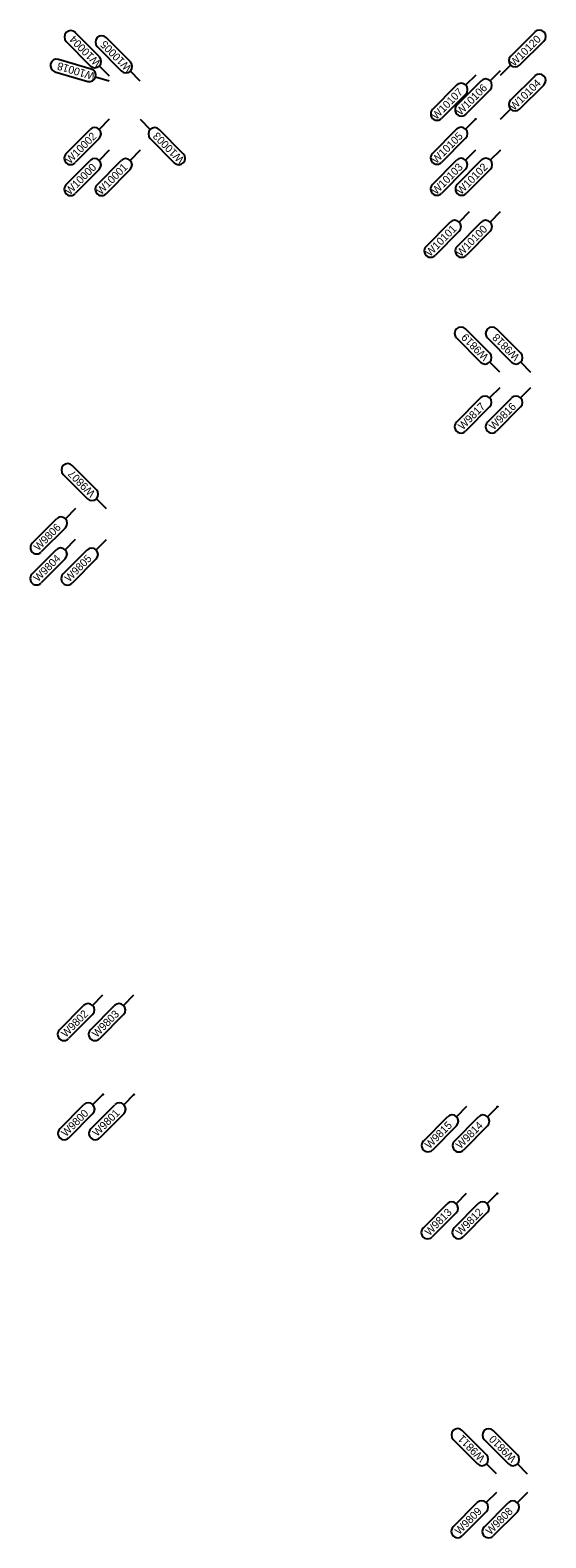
# Model space of a CAD drawing. Extents: x 12479652 to 12487250, y 9842710 to 9846560.
# Drawn here: x 12483665.7 to 12483748.9, y 9844668.9 to 9844912 of the extents above; entities that cross this region are included whole.
import ezdxf

# ---------------------------------------------------------------- set-up
doc = ezdxf.new("R2010")
doc.units = 0
doc.layers.add('Default', color=7, linetype='Continuous')
doc.layers.add('TextAlignmentLrg', color=7, linetype='Continuous')

msp = doc.modelspace()

# ---------------------------------------------------------------- linework, layer by layer
at = {"layer": 'Default'}
for p, q in [((12483676.91, 9844907.74), (12483673.03, 9844911.66)), ((12483681.91, 9844906.91), (12483678.03, 9844910.84)), ((12483747.18, 9844911.75), (12483743.26, 9844907.87)), ((12483671.57, 9844910.22), (12483675.45, 9844906.29)), ((12483676.57, 9844909.39), (12483680.45, 9844905.47)), ((12483744.7, 9844906.41), (12483748.62, 9844910.29)), ((12483675.61, 9844905.75), (12483670.32, 9844907.31)), ((12483678.52, 9844904.65), (12483676.9, 9844906.28)), ((12483741.61, 9844904.8), (12483743.25, 9844906.42)), ((12483669.74, 9844905.34), (12483675.03, 9844903.79)), ((12483678.51, 9844903.83), (12483676.31, 9844904.48)), ((12483683.51, 9844903.82), (12483681.9, 9844905.46)), ((12483734.59, 9844899.95), (12483738.48, 9844903.87)), ((12483737.61, 9844904.81), (12483735.99, 9844903.18)), ((12483741.55, 9844905.5), (12483739.93, 9844903.87)), ((12483747.17, 9844904.65), (12483743.25, 9844900.78)), ((12483730.65, 9844899.26), (12483734.54, 9844903.18)), ((12483736, 9844901.73), (12483732.11, 9844897.82)), ((12483739.93, 9844902.42), (12483736.04, 9844898.51)), ((12483744.69, 9844899.32), (12483748.61, 9844903.19)), ((12483741.6, 9844897.71), (12483743.24, 9844899.32)), ((12483678.51, 9844897.68), (12483676.88, 9844896.05)), ((12483683.51, 9844897.67), (12483685.12, 9844896.03)), ((12483737.6, 9844897.71), (12483735.98, 9844896.08)), ((12483671.54, 9844892.13), (12483675.43, 9844896.04)), ((12483676.89, 9844894.59), (12483673, 9844890.68)), ((12483685.11, 9844894.58), (12483688.99, 9844890.66)), ((12483690.45, 9844892.1), (12483686.57, 9844896.02)), ((12483730.64, 9844892.17), (12483734.53, 9844896.08)), ((12483735.99, 9844894.63), (12483732.1, 9844890.72)), ((12483678.5, 9844892.68), (12483676.88, 9844891.05)), ((12483683.5, 9844892.67), (12483681.88, 9844891.04)), ((12483737.59, 9844892.71), (12483735.97, 9844891.08)), ((12483741.59, 9844892.71), (12483739.97, 9844891.08)), ((12483671.54, 9844887.13), (12483675.42, 9844891.04)), ((12483676.88, 9844889.59), (12483672.99, 9844885.68)), ((12483676.54, 9844887.12), (12483680.42, 9844891.03)), ((12483681.88, 9844889.59), (12483677.99, 9844885.67)), ((12483730.63, 9844887.17), (12483734.52, 9844891.08)), ((12483735.98, 9844889.63), (12483732.09, 9844885.72)), ((12483734.63, 9844887.16), (12483738.52, 9844891.07)), ((12483739.98, 9844889.63), (12483736.09, 9844885.71)), ((12483736.56, 9844882.72), (12483734.94, 9844881.08)), ((12483741.56, 9844882.72), (12483739.94, 9844881.08)), ((12483729.6, 9844877.17), (12483733.49, 9844881.08)), ((12483734.95, 9844879.63), (12483731.06, 9844875.72)), ((12483734.6, 9844877.17), (12483738.49, 9844881.08)), ((12483739.95, 9844879.63), (12483736.06, 9844875.72)), ((12483734.53, 9844862.42), (12483738.41, 9844858.51)), ((12483739.87, 9844859.95), (12483735.98, 9844863.87)), ((12483739.53, 9844862.41), (12483743.41, 9844858.49)), ((12483744.87, 9844859.94), (12483740.98, 9844863.85)), ((12483741.49, 9844856.87), (12483739.87, 9844858.5)), ((12483746.49, 9844856.86), (12483744.87, 9844858.49)), ((12483734.52, 9844848.82), (12483738.41, 9844852.74)), ((12483739.52, 9844848.81), (12483743.41, 9844852.72)), ((12483741.48, 9844854.37), (12483739.86, 9844852.74)), ((12483746.48, 9844854.36), (12483744.86, 9844852.73)), ((12483739.86, 9844851.29), (12483735.97, 9844847.38)), ((12483744.86, 9844851.28), (12483740.97, 9844847.36)), ((12483671.08, 9844840.39), (12483674.97, 9844836.48)), ((12483676.43, 9844837.92), (12483672.54, 9844841.84)), ((12483678.04, 9844834.84), (12483676.42, 9844836.47)), ((12483666.08, 9844829.33), (12483669.97, 9844833.25)), ((12483673.04, 9844834.88), (12483671.42, 9844833.25)), ((12483671.43, 9844831.8), (12483667.54, 9844827.89)), ((12483666.04, 9844824.33), (12483669.93, 9844828.25)), ((12483671.04, 9844824.29), (12483674.93, 9844828.21)), ((12483673, 9844829.88), (12483671.38, 9844828.25)), ((12483678, 9844829.84), (12483676.38, 9844828.21)), ((12483671.39, 9844826.8), (12483667.5, 9844822.89)), ((12483676.39, 9844826.76), (12483672.5, 9844822.85)), ((12483677.44, 9844756.39), (12483675.81, 9844754.76)), ((12483682.44, 9844756.39), (12483680.81, 9844754.75)), ((12483670.47, 9844750.84), (12483674.36, 9844754.76)), ((12483675.82, 9844753.31), (12483671.93, 9844749.4)), ((12483675.47, 9844750.84), (12483679.36, 9844754.75)), ((12483680.82, 9844753.3), (12483676.93, 9844749.39)), ((12483670.52, 9844734.84), (12483674.41, 9844738.76)), ((12483675.52, 9844734.84), (12483679.41, 9844738.75)), ((12483677.48, 9844740.39), (12483675.86, 9844738.76)), ((12483682.48, 9844740.38), (12483680.86, 9844738.75)), ((12483736.13, 9844738.44), (12483734.51, 9844736.81)), ((12483741.13, 9844738.43), (12483739.51, 9844736.8)), ((12483675.87, 9844737.31), (12483671.98, 9844733.4)), ((12483680.87, 9844737.3), (12483676.98, 9844733.39)), ((12483729.17, 9844732.89), (12483733.06, 9844736.8)), ((12483734.17, 9844732.88), (12483738.06, 9844736.8)), ((12483734.52, 9844735.36), (12483730.63, 9844731.44)), ((12483739.52, 9844735.35), (12483735.63, 9844731.44)), ((12483736.09, 9844724.41), (12483734.47, 9844722.78)), ((12483741.09, 9844724.43), (12483739.47, 9844722.8)), ((12483729.13, 9844718.86), (12483733.02, 9844722.77)), ((12483734.47, 9844721.33), (12483730.58, 9844717.42)), ((12483734.13, 9844718.88), (12483738.02, 9844722.8)), ((12483739.47, 9844721.35), (12483735.58, 9844717.44)), ((12483733.99, 9844684.75), (12483737.88, 9844680.84)), ((12483739.34, 9844682.29), (12483735.45, 9844686.2)), ((12483738.99, 9844684.74), (12483742.88, 9844680.83)), ((12483744.34, 9844682.27), (12483740.45, 9844686.19)), ((12483740.95, 9844679.21), (12483739.33, 9844680.84)), ((12483745.95, 9844679.19), (12483744.33, 9844680.82)), ((12483740.95, 9844676.21), (12483739.32, 9844674.57)), ((12483745.95, 9844676.19), (12483744.32, 9844674.56)), ((12483733.98, 9844670.66), (12483737.87, 9844674.57)), ((12483739.33, 9844673.12), (12483735.44, 9844669.21)), ((12483738.98, 9844670.64), (12483742.87, 9844674.56)), ((12483744.33, 9844673.11), (12483740.44, 9844669.2))]:
    msp.add_line(p, q, dxfattribs=at)
for centre, start, end in [((12483672.3, 9844910.94), 44.6553, 224.6553), ((12483677.3, 9844910.11), 44.6553, 224.6553), ((12483747.9, 9844911.02), 314.6553, 134.6553), ((12483670.03, 9844906.33), 73.5965, 253.5965), ((12483676.18, 9844907.01), 224.6553, 44.6553), ((12483681.18, 9844906.19), 224.6553, 44.6553), ((12483743.98, 9844907.14), 134.6553, 314.6553), ((12483675.32, 9844904.77), 253.5965, 73.5965), ((12483735.27, 9844902.45), 315.1702, 135.1702), ((12483739.21, 9844903.14), 315.1702, 135.1702), ((12483747.89, 9844903.92), 314.6553, 134.6553), ((12483731.38, 9844898.54), 135.1702, 315.1702), ((12483735.32, 9844899.23), 135.1702, 315.1702), ((12483743.97, 9844900.05), 134.6553, 314.6553), ((12483676.16, 9844895.32), 315.1702, 135.1702), ((12483685.84, 9844895.3), 44.6553, 224.6553), ((12483735.26, 9844895.35), 315.1702, 135.1702), ((12483672.27, 9844891.4), 135.1702, 315.1702), ((12483676.15, 9844890.32), 315.1702, 135.1702), ((12483681.15, 9844890.31), 315.1702, 135.1702), ((12483689.72, 9844891.38), 224.6553, 44.6553), ((12483731.37, 9844891.44), 135.1702, 315.1702), ((12483735.25, 9844890.35), 315.1702, 135.1702), ((12483739.25, 9844890.35), 315.1702, 135.1702), ((12483672.26, 9844886.4), 135.1702, 315.1702), ((12483677.26, 9844886.4), 135.1702, 315.1702), ((12483731.36, 9844886.44), 135.1702, 315.1702), ((12483735.36, 9844886.44), 135.1702, 315.1702), ((12483734.22, 9844880.36), 315.1702, 135.1702), ((12483739.22, 9844880.36), 315.1702, 135.1702), ((12483730.33, 9844876.44), 135.1702, 315.1702), ((12483735.33, 9844876.44), 135.1702, 315.1702), ((12483735.25, 9844863.14), 44.8253, 224.8253), ((12483740.25, 9844863.13), 44.8253, 224.8253), ((12483739.14, 9844859.23), 224.8253, 44.8253), ((12483744.14, 9844859.22), 224.8253, 44.8253), ((12483739.13, 9844852.01), 315.1702, 135.1702), ((12483744.13, 9844852), 315.1702, 135.1702), ((12483735.25, 9844848.1), 135.1702, 315.1702), ((12483740.25, 9844848.09), 135.1702, 315.1702), ((12483671.81, 9844841.11), 44.8253, 224.8253), ((12483675.7, 9844837.2), 224.8253, 44.8253), ((12483670.7, 9844832.52), 315.1702, 135.1702), ((12483666.81, 9844828.61), 135.1702, 315.1702), ((12483670.66, 9844827.52), 315.1702, 135.1702), ((12483675.66, 9844827.48), 315.1702, 135.1702), ((12483666.77, 9844823.61), 135.1702, 315.1702), ((12483671.77, 9844823.57), 135.1702, 315.1702), ((12483675.09, 9844754.03), 315.1702, 135.1702), ((12483680.09, 9844754.03), 315.1702, 135.1702), ((12483671.2, 9844750.12), 135.1702, 315.1702), ((12483676.2, 9844750.11), 135.1702, 315.1702), ((12483675.14, 9844738.03), 315.1702, 135.1702), ((12483680.14, 9844738.03), 315.1702, 135.1702), ((12483733.79, 9844736.08), 315.1702, 135.1702), ((12483738.79, 9844736.07), 315.1702, 135.1702), ((12483671.25, 9844734.12), 135.1702, 315.1702), ((12483676.25, 9844734.11), 135.1702, 315.1702), ((12483729.9, 9844732.17), 135.1702, 315.1702), ((12483734.9, 9844732.16), 135.1702, 315.1702), ((12483733.75, 9844722.05), 315.1702, 135.1702), ((12483738.75, 9844722.07), 315.1702, 135.1702), ((12483729.86, 9844718.14), 135.1702, 315.1702), ((12483734.86, 9844718.16), 135.1702, 315.1702), ((12483734.72, 9844685.48), 44.8253, 224.8253), ((12483739.72, 9844685.46), 44.8253, 224.8253), ((12483738.61, 9844681.56), 224.8253, 44.8253), ((12483743.61, 9844681.55), 224.8253, 44.8253), ((12483738.6, 9844673.85), 315.1702, 135.1702), ((12483743.6, 9844673.83), 315.1702, 135.1702), ((12483734.71, 9844669.93), 135.1702, 315.1702), ((12483739.71, 9844669.92), 135.1702, 315.1702)]:
    msp.add_arc(centre, 1.03, start, end, dxfattribs=at)
at = {"layer": 'TextAlignmentLrg'}
for centre in [(12483737.6, 9844897.71), (12483677.48, 9844740.39), (12483682.48, 9844740.38), (12483741.13, 9844738.43), (12483741.09, 9844724.43)]:
    msp.add_circle(centre, 0.05, dxfattribs=at)

# ---------------------------------------------------------------- texts
at = {"layer": 'Default'}
for s, rotation, p in [('W10004', 134.6553, (12483677.23, 9844906.86)), ('W10120', 44.6553, (12483743.83, 9844906.1)), ('W10005', 134.6553, (12483682.21, 9844906.05)), ('W10018', 163.5965, (12483676.31, 9844905.14)), ('W10106', 45.1702, (12483735.19, 9844898.21)), ('W10104', 44.6553, (12483743.81, 9844899)), ('W10107', 45.1702, (12483731.27, 9844897.53)), ('W10002', 45.1702, (12483672.17, 9844890.4)), ('W10003', 134.6553, (12483690.68, 9844891.28)), ('W10105', 45.1702, (12483731.26, 9844890.43)), ('W10000', 45.1702, (12483672.14, 9844885.38)), ('W10001', 45.1702, (12483677.18, 9844885.41)), ('W10103', 45.1702, (12483731.25, 9844885.43)), ('W10102', 45.1702, (12483735.26, 9844885.43)), ('W10101', 45.1702, (12483730.25, 9844875.46)), ('W10100', 45.1702, (12483735.21, 9844875.42)), ('W9819', 134.8253, (12483739.79, 9844859.48)), ('W9818', 134.8253, (12483744.79, 9844859.46)), ('W9817', 45.1702, (12483735.53, 9844847.48)), ('W9816', 45.1702, (12483740.51, 9844847.46)), ('W9807', 134.8253, (12483676.34, 9844837.46)), ('W9806', 45.1702, (12483667.08, 9844827.98)), ('W9804', 45.1702, (12483667.03, 9844822.98)), ('W9805', 45.1702, (12483672.05, 9844822.96)), ('W9802', 45.1702, (12483671.49, 9844749.51)), ('W9803', 45.1702, (12483676.48, 9844749.49)), ('W9800', 45.1702, (12483671.52, 9844733.49)), ('W9801', 45.1702, (12483676.56, 9844733.52)), ('W9815', 45.1702, (12483730.18, 9844731.55)), ('W9814', 45.1702, (12483735.16, 9844731.53)), ('W9813', 45.1702, (12483730.14, 9844717.52)), ('W9812', 45.1702, (12483735.15, 9844717.55)), ('W9811', 134.8253, (12483739.23, 9844681.85)), ('W9810', 134.8253, (12483744.26, 9844681.8)), ('W9809', 45.1702, (12483734.98, 9844669.31)), ('W9808', 45.1702, (12483739.98, 9844669.29))]:
    msp.add_text(s, height=1.25, rotation=rotation, dxfattribs=at).set_placement(p)

doc.saveas('drawing.dxf')
